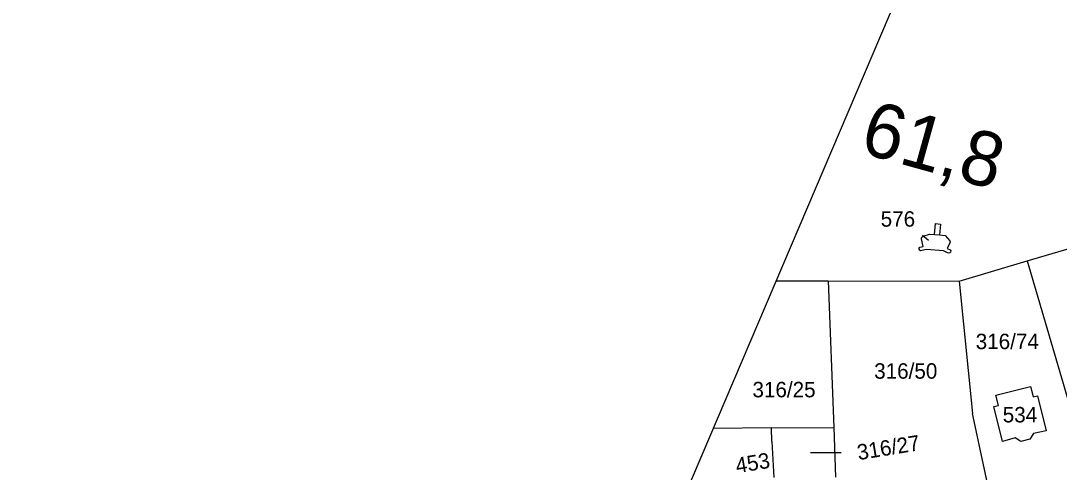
# Model space of a CAD drawing. Extents: x -805826 to -803822, y -1165880 to -1164382.
# Drawn here: x -805826.1 to -805597.3, y -1164820.3 to -1164720.9 of the extents above; entities that cross this region are included whole.
import ezdxf

# ---------------------------------------------------------------- set-up
doc = ezdxf.new("R2010")
doc.units = 0
for name, color, linetype in [('formát', 7, 'Continuous'), ('kilometráž - 2880', 7, 'Continuous'), ('kn_celek - Cisla parcel pomocna', 7, 'Continuous'), ('kn_celek - Cisla pozemkovych parcel', 7, 'Continuous'), ('kn_celek - Cisla stavebnich parcel', 7, 'Continuous'), ('kn_celek - Hranice parcel', 7, 'Continuous'), ('kn_celek - Vnitrni kresby', 7, 'Continuous')]:
    doc.layers.add(name, color=color, linetype=linetype)

msp = doc.modelspace()

# ---------------------------------------------------------------- linework, layer by layer
at = {"layer": 'formát'}
msp.add_line((-805491.17, -1164382.07), (-805826.05, -1165169.15), dxfattribs=at)
at = {"layer": 'kn_celek - Cisla parcel pomocna'}
for p, q in [((-805626.12, -1164769.24), (-805627.44, -1164768.15)), ((-805652.13, -1164815.97), (-805645.39, -1164815.98))]:
    msp.add_line(p, q, dxfattribs=at)
at = {"layer": 'kn_celek - Hranice parcel'}
for p, q in [((-805624.82, -1164767.96), (-805624.58, -1164765.56)), ((-805624.58, -1164765.56), (-805623.47, -1164765.67)), ((-805623.47, -1164765.67), (-805623.74, -1164768.05)), ((-805604.38, -1164773.78), (-805575.61, -1164765.21)), ((-805627.69, -1164768.93), (-805627.67, -1164768.75)), ((-805627.27, -1164770.56), (-805627.69, -1164768.93)), ((-805627.67, -1164768.75), (-805627.56, -1164768.53)), ((-805627.56, -1164768.53), (-805627.31, -1164768.35)), ((-805627.31, -1164768.35), (-805625.91, -1164767.86)), ((-805625.91, -1164767.86), (-805624.82, -1164767.96)), ((-805623.74, -1164768.05), (-805622.45, -1164768.16)), ((-805622.45, -1164768.16), (-805621.45, -1164769.34)), ((-805628.19, -1164771.18), (-805628.15, -1164770.95)), ((-805628.07, -1164771.42), (-805628.19, -1164771.18)), ((-805628.15, -1164770.95), (-805628, -1164770.76)), ((-805628, -1164770.76), (-805627.27, -1164770.56)), ((-805626.58, -1164771.24), (-805627.6, -1164771.5)), ((-805622.84, -1164771.51), (-805626.58, -1164771.24)), ((-805621.42, -1164769.79), (-805622.02, -1164771)), ((-805622.02, -1164771), (-805621.37, -1164771.33)), ((-805621.45, -1164769.34), (-805621.38, -1164769.59)), ((-805621.38, -1164769.59), (-805621.42, -1164769.79)), ((-805621.37, -1164771.33), (-805621.22, -1164771.56)), ((-805627.87, -1164771.52), (-805628.07, -1164771.42)), ((-805627.6, -1164771.5), (-805627.87, -1164771.52)), ((-805621.94, -1164771.96), (-805622.84, -1164771.51)), ((-805621.68, -1164772.05), (-805621.94, -1164771.96)), ((-805621.45, -1164772), (-805621.68, -1164772.05)), ((-805621.29, -1164771.83), (-805621.45, -1164772)), ((-805621.22, -1164771.56), (-805621.29, -1164771.83)), ((-805619.36, -1164778.25), (-805604.38, -1164773.78)), ((-805604.38, -1164773.78), (-805593.22, -1164811.82)), ((-805659.69, -1164778.15), (-805650.86, -1164778.17)), ((-805650.86, -1164778.17), (-805648.21, -1164778.17)), ((-805648.21, -1164778.17), (-805619.36, -1164778.25)), ((-805648.21, -1164778.17), (-805647.01, -1164810.45)), ((-805619.36, -1164778.25), (-805616.42, -1164807.4)), ((-805611.31, -1164803.32), (-805603.66, -1164801.46)), ((-805610.74, -1164805.6), (-805611.31, -1164803.32)), ((-805603.66, -1164801.46), (-805603.09, -1164803.72)), ((-805611.71, -1164805.85), (-805610.74, -1164805.6)), ((-805603.09, -1164803.72), (-805602.09, -1164803.51)), ((-805602.09, -1164803.51), (-805600.21, -1164811.18)), ((-805609.8, -1164838.08), (-805616.42, -1164807.4)), ((-805609.82, -1164813.55), (-805611.71, -1164805.85)), ((-805660.68, -1164810.58), (-805673.55, -1164810.72)), ((-805660.68, -1164810.58), (-805647.01, -1164810.45)), ((-805660.61, -1164813.52), (-805660.68, -1164810.58)), ((-805647.01, -1164810.45), (-805646.59, -1164821.44)), ((-805603.02, -1164811.81), (-805603.81, -1164813.05)), ((-805600.21, -1164811.18), (-805603.02, -1164811.81)), ((-805660.61, -1164813.52), (-805660.2, -1164821.47)), ((-805607.02, -1164812.76), (-805609.82, -1164813.55)), ((-805605.81, -1164813.56), (-805607.02, -1164812.76)), ((-805603.81, -1164813.05), (-805605.81, -1164813.56))]:
    msp.add_line(p, q, dxfattribs=at)
at = {"layer": 'kn_celek - Vnitrni kresby'}
msp.add_line((-805624.82, -1164767.96), (-805623.74, -1164768.05), dxfattribs=at)

# ---------------------------------------------------------------- texts
at = {"layer": 'kilometráž - 2880'}
msp.add_text('61,8', height=12, rotation=344.4806, dxfattribs=at).set_placement((-805641.63, -1164749.79))
at = {"layer": 'kn_celek - Cisla parcel pomocna'}
msp.add_text('576', height=3.4, dxfattribs=at).set_placement((-805636.66, -1164766.22))
for s, rotation, p in [('316/27', 9.225, (-805641.55, -1164817.67)), ('453', 9.63, (-805668.31, -1164820.58))]:
    msp.add_text(s, height=3.4, rotation=rotation, dxfattribs=at).set_placement(p)
at = {"layer": 'kn_celek - Cisla pozemkovych parcel'}
for s, height, p in [('316/74', 3.4, (-805615.73, -1164793.21)), ('316/50', 3.4, (-805638.09, -1164799.72)), ('316/25', 3.4, (-805664.9, -1164803.82)), ('316/27', 0.005, (-805652.13, -1164815.97))]:
    msp.add_text(s, height=height, dxfattribs=at).set_placement(p)
at = {"layer": 'kn_celek - Cisla stavebnich parcel'}
for s, height, p in [('576', 0.005, (-805626.12, -1164769.24)), ('534', 3.4, (-805609.78, -1164809.35))]:
    msp.add_text(s, height=height, dxfattribs=at).set_placement(p)

doc.saveas('drawing.dxf')
